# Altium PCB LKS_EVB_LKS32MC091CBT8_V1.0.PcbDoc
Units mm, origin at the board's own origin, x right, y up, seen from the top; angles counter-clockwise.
Board outline 67 x 40.5 mm, 2 copper layers (Top Layer, Bottom Layer); 59 components, 69 nets, 218 pads, 289 vias.
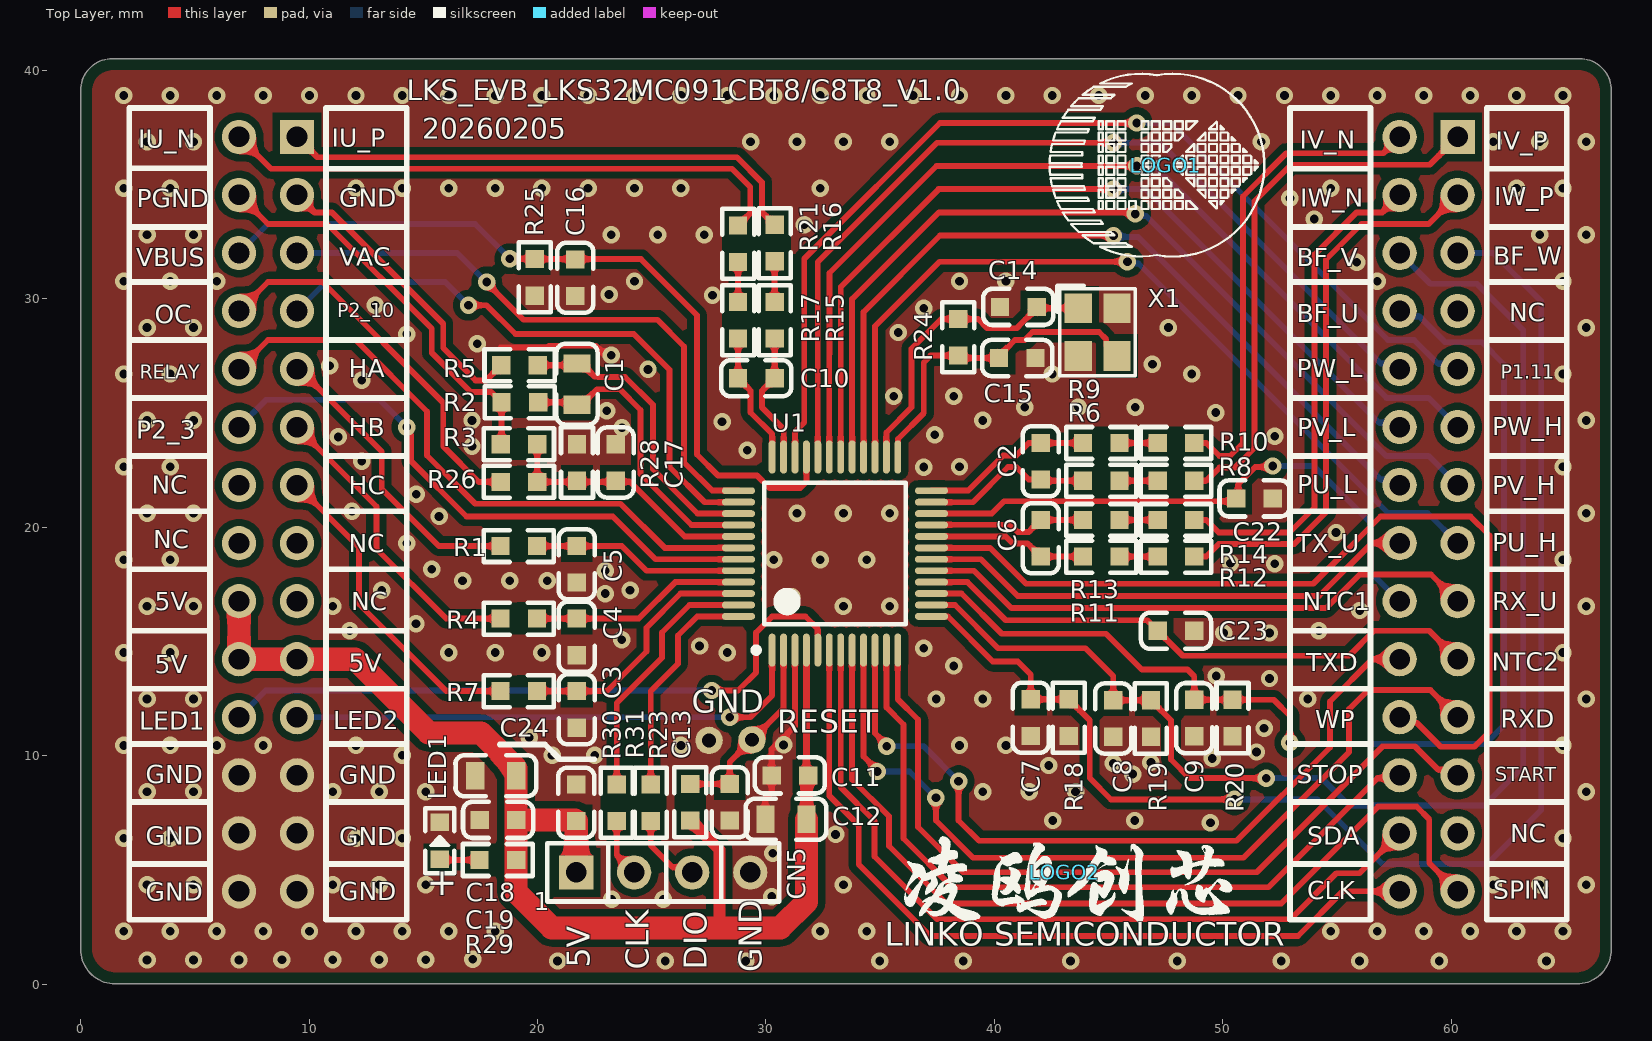
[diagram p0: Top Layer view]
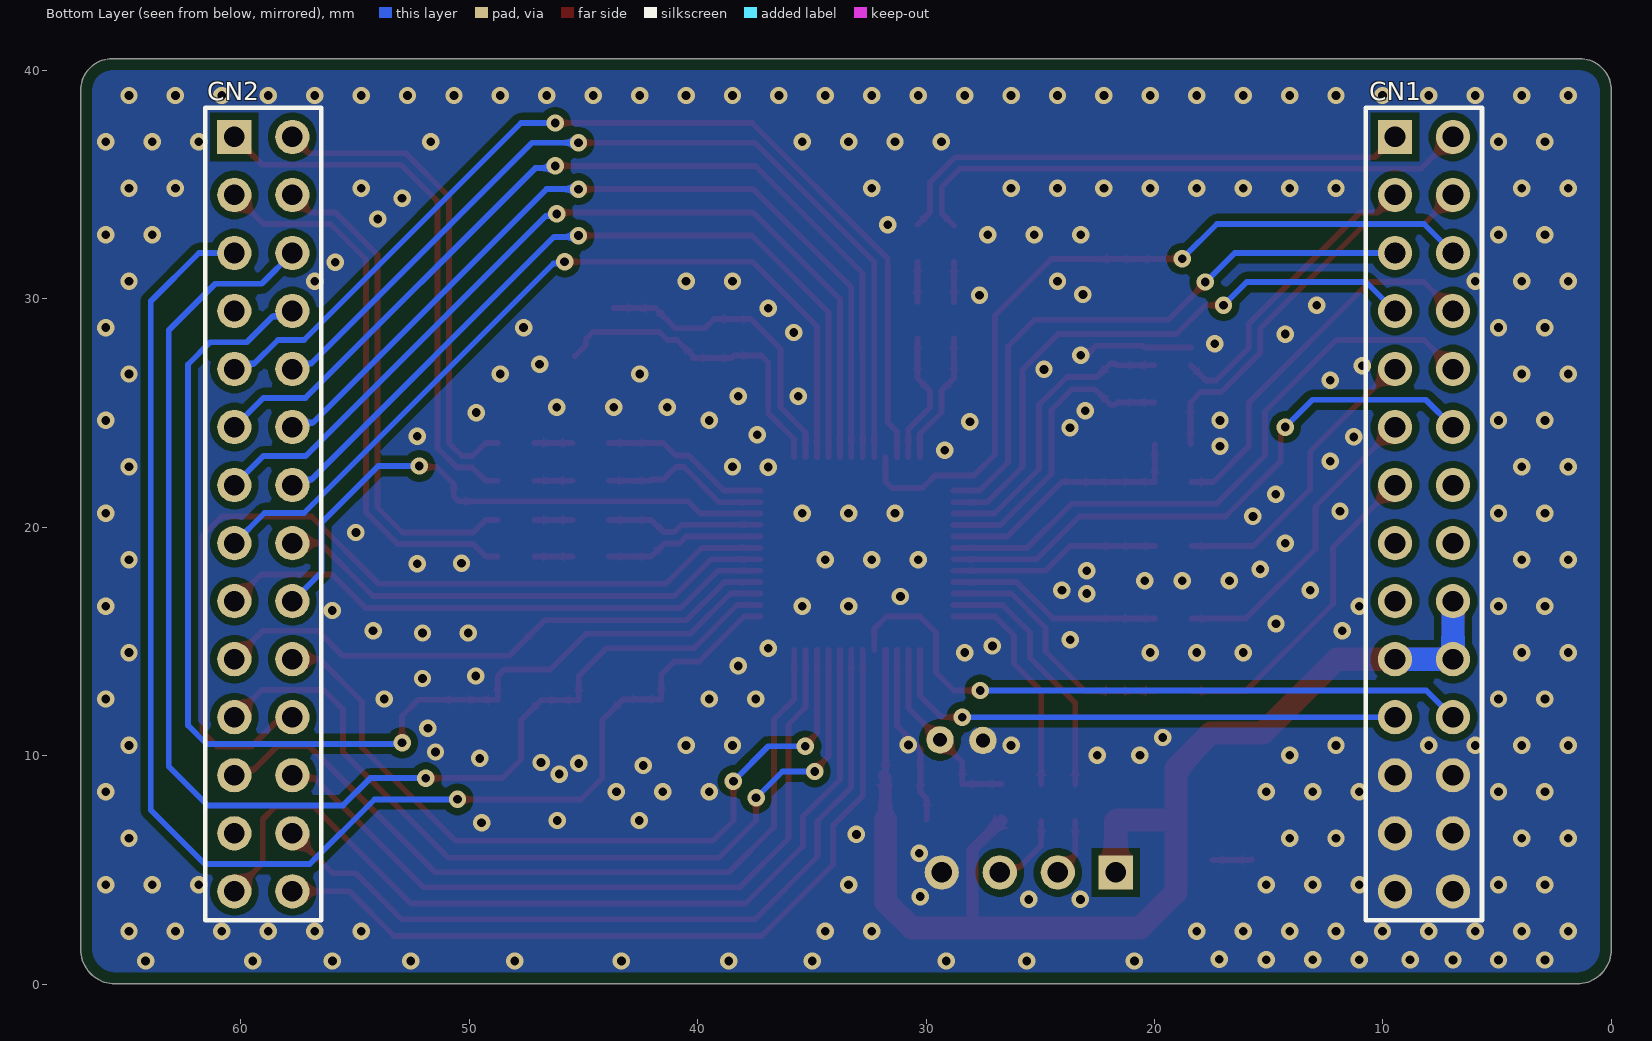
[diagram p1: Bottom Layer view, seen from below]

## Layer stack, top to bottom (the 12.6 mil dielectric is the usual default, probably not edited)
Top Solder: solder mask 0.0102, Solder Resist, Dk 3.5
Top Layer: signal copper 0.0356
Dielectric1: dielectric 0.32, FR-4, Dk 4.8
Bottom Layer: signal copper 0.0356
Bottom Solder: solder mask 0.0102, Solder Resist, Dk 3.5

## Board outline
0,1.533 0,39.116 cw(c1.397,39.116) 1.397,40.513 65.608,40.513 cw(c65.608,39.116) 67.005,39.116 67.005,1.533 cw(c65.481,1.533) 65.481,0.009 1.524,0.009 cw(c1.524,1.533)

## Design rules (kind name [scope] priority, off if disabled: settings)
BoardOutlineClearance [All] p1: gap=0.508 ignorepadtopadclearanceinfootprint=FALSE
Clearance [InPolygon] p1: gap=0.305 ignorepadtopadclearanceinfootprint=FALSE
Clearance InMCU [WithinRoom('MCU')] p2: gap=0.147 ignorepadtopadclearanceinfootprint=FALSE
Clearance Clearance_1 [All] p3: gap=0.254 ignorepadtopadclearanceinfootprint=FALSE
ComponentClearance [All] p1: gap=0 collisioncheckmode=3 verticalgap=0 showdistances=FALSE
DiffPairsRouting [All] p1: maxlimit=0.254 minlimit=0.254 mostfreqgap=0.254 toplayer_minwidth=0.254 toplayer_maxwidth=0.381 toplayer_prefwidth=0.254 bottomlayer_minwidth=0.254 bottomlayer_maxwidth=0.381 bottomlayer_prefwidth=0.254 maxuncoupledlength=12.7
FabricationTestpoint [(IsPad And (OnTopLayer Or OnBottomLayer))] p1: side=3 testpointundercomponent=TRUE minsize=1.016 maxsize=2.54 preferedsize=1.524 minholesize=0 maxholesize=1.016 preferedholesize=0.813 testpointgrid=0.025 allowsidetop=TRUE allowsidebottom=TRUE usegrid=TRUE gridtolerance=0
HoleSize [All] p1: absolutevalues=TRUE maxlimit=2.54 minlimit=0 maxpercent=80.000 minpercent=20.000
PolygonConnect [All] p1: connectstyle=Direct reliefconductorwidth=0.254 reliefentries=4 polygonreliefangle="90 Angle" airgapwidth=0.254
RoomDefinition MCU [False] p1: confinementstyle=ConfineIn formatcopy=TRUE lockcomponents=FALSE outline 19.787,37.287 41.199,37.287 41.199,1.168 19.787,1.168
RoutingVias [All] p1: holewidth=0.711 width=1.27 viastyle="Through Hole" minholewidth=0 minwidth=0.254 maxholewidth=0.711 maxwidth=1.27
SilkToSilkClearance [All] p1: silktosilkclearance=0.025
SilkToSolderMaskClearance [IsPad] p1: minsilkscreentomaskgap=0 clearancetoexposedcopper=FALSE
SilkToSolderMaskClearance SilkscreenOverComponentPads [IsPad] p2: minsilkscreentomaskgap=0.254 clearancetoexposedcopper=TRUE
SolderMaskExpansion [All] p1: expansion=0.102 istentingtop=FALSE
SupplyNets "Schematic Supply Nets_1" [InNet('GND')] p1: voltage=0.000
SupplyNets "Schematic Supply Nets" [InNet('+5V')] p2: voltage=0.000
Width [All] p1: maxlimit=2.54 minlimit=0.254 preferedwidth=0.254 minimp=50.000000 maximp=50.000000 favimp=50.000000
24 further rules are at their usual default settings.

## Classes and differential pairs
differential pair SHUNT_W: +SHUNT_W_P -SHUNT_W_N
differential pair SHUNT_V: +SHUNT_V_P -SHUNT_V_N
differential pair SHUNT_U: +SHUNT_U_P -SHUNT_U_N
differential pair OP_IW: +OP_IW_P -OP_IW_N
differential pair OP_IV: +OP_IV_P -OP_IV_N
differential pair OP_IU: +OP_IU_P -OP_IU_N
differential pair OP_IBUS: +OP_IBUS_P -OP_IBUS_N

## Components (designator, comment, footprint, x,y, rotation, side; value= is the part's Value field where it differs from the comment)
C1 "1uF/0805/50V" C0805S 21.729,26.264 r270 top
C2 "100pF/0603/50V" C0603S 42.025,22.887 r270 top
C3 "10nF/0603/50V" C0603S 21.719,12.027 r90 top
C4 "10nF/0603/50V" C0603S 21.717,15.202 r90 top
C5 "10nF/0603/50V" C0603S 21.719,18.377 r90 top
C6 "100pF/0603/50V" C0603S 42.025,19.516 r270 top
C7 "1nF/0603/50V" C0603S 41.591,11.666 r90 top
C8 "1nF/0603/50V" C0603S 45.197,11.628 r90 top
C9 "1nF/0603/50V" C0603S 48.75,11.646 r90 top
C10 "100pF/0603/50V" C0603S 29.578,26.518 r0 top
C11 "100nF/0603/50V" C0603S 31.047,9.136 r180 top
C12 "10uF/0805/25V" C0805S 30.875,7.214 r180 top
C13 "100nF/0603/50V" C0603S 28.414,7.963 r90 top
C14 "10pF/0603/50V/C0G" C0603S 41.046,29.642 r0 top
C15 "10pF/0603/50V/C0G" C0603S 40.996,27.407 r180 top
C16 "100nF/0603/50V" C0603S 21.656,30.918 r90 top
C17 "1nF/0603/50V" C0603S 23.419,22.835 r270 top
C18 "10uF/0805/25V" C0805S 18.175,9.123 r0 top
C19 "100nF/0603/50V" C0603S 18.275,7.188 r0 top
C22 "100nF/0603/50V" C0603S 51.384,21.26 r180 top
C23 "100nF/0603/50V" C0603S 47.947,15.469 r180 top
C24 "100nF/0603/50V" C0603S 21.692,7.938 r90 top
CN1 "HDR-2*14P-2.54" HDR2X14/2.54-F-B 9.474,37.084 r270 bottom
CN2 "HDR-2*14P-2.54" HDR2X14/2.54-F-B 60.274,37.084 r270 bottom
CN5 "HDR-1*4P-2.54" HDR-1*4P-2.54 26.772,4.89 r0 top
LED1 "RED" LED0603 15.723,5.461 r270 top
LOGO1 "LKS_sign" LKS_LOGO2 47.473,35.839 r0 top
LOGO2 "LKS_sign" LKS_LOGO1 43.053,4.902 r0 top
R1 "1K/0603/±5%" R0603S 19.177,19.177 r0 top
R2 "1K/0603/±1%" R0603S 19.227,25.464 r0 top
R3 "1K/0603/±1%" R0603S 19.187,23.634 r180 top
R4 "1K/0603/±5%" R0603S 19.177,16.002 r0 top
R5 "1K/0603/±1%" R0603S 19.214,27.09 r0 top
R6 "0R/0603/±5%" R0603S 44.671,22.036 r180 top
R7 "1K/0603/±5%" R0603S 19.177,12.827 r0 top
R8 "1K/0603/±1%" R0603S 47.947,22.036 r180 top
R9 "0R/0603/±5%" R0603S 44.671,23.687 r180 top
R10 "1K/0603/±1%" R0603S 47.947,23.687 r180 top
R11 "0R/0603/±5%" R0603S 44.671,18.716 r180 top
R12 "1K/0603/±1%" R0603S 47.947,18.716 r180 top
R13 "0R/0603/±5%" R0603S 44.671,20.316 r180 top
R14 "1K/0603/±1%" R0603S 47.947,20.316 r180 top
R15 "0R/0603/±5%" R0603S 30.378,29.058 r270 top
R16 "1K/0603/±1%" R0603S 30.378,32.436 r270 top
R17 "0R/0603/±5%" R0603S 28.778,29.058 r270 top
R18 "1K/0603/±1%" R0603S 43.254,11.666 r90 top
R19 "1K/0603/±1%" R0603S 46.848,11.628 r90 top
R20 "1K/0603/±1%" R0603S 50.419,11.646 r90 top
R21 "1K/0603/±1%" R0603S 28.778,32.41 r270 top
R23 "10K/0603/±5%" R0603S 26.683,7.963 r270 top
R24 "1M/0603/±5%" R0603S 38.417,28.312 r90 top
R25 "1K/0603/±1%" R0603S 19.877,30.937 r90 top
R26 "1K/0603/±1%" R0603S 19.187,21.983 r0 top
R28 "10K/0603/±1%" R0603S 21.729,22.834 r270 top
R29 "1K/0603/±5%" R0603S 18.264,5.435 r180 top
R30 "100R/0603/±5%" R0603S 23.47,7.938 r270 top
R31 "100R/0603/±5%" R0603S 24.957,7.938 r270 top
U1 "LKS32MC091CBT8/C8T8" "TQFP48 7x7" 33.02,18.847 r90 top
X1 "8MHz" XTAL-SMD3225 44.513,28.541 r270 top

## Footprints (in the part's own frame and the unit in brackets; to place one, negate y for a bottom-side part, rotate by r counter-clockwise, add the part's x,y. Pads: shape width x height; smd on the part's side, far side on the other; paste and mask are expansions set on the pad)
C0603S [mm]
  rect 0.8x0.8 smd: 1(-0.8,0) 2(0.8,0)
  silkscreen extent -1.53,-0.79 1.54,0.79, body extent -0.8,-0.4 0.8,0.4, height 0.3
C0805S [mm]
  rect 0.8x1.2 smd: 1(-0.9,0) 2(0.9,0)
  silkscreen extent -1.77,-0.9 1.77,0.9, body extent -1,-0.62 1,0.63, height 0.77
HDR2X14/2.54-F-B [mm] "Connector; Header; 14x2 Position"
  rect 1.5x1.5 hole 0.9: 1(0,0)
  round 1.5 hole 0.9: 2(0,2.54) 3(2.54,0) 4(2.54,2.54) 5(5.08,0) 6(5.08,2.54) 7(7.62,0) 8(7.62,2.54) 9(10.16,0) 10(10.16,2.54) 11(12.7,0) 12(12.7,2.54) 13(15.24,0) 14(15.24,2.54) 15(17.78,0) 16(17.78,2.54) 17(20.32,0) 18(20.32,2.54) 19(22.86,0) 20(22.86,2.54) 21(25.4,0) 22(25.4,2.54) 23(27.94,0) 24(27.94,2.54) 25(30.48,0) 26(30.48,2.54) 27(33.02,0) 28(33.02,2.54)
  silkscreen extent -1.27,-1.27 34.29,3.81, body extent -1.27,-1.27 34.29,3.81, height 8.5
HDR-1*4P-2.54 [mm]
  rect 1.5x1.5 hole 0.9: 1(-5.08,0)
  round 1.5 hole 0.9: 2(-2.54,0) 3(0,0) 4(2.54,0)
  silkscreen extent -6.35,-1.27 3.81,1.27, body extent -6.22,-1.27 3.94,1.27, height 8.54
LED0603 [mil]
  rect 30x32 smd: 1(0,0) 2(-64,0)
  silkscreen extent -88,-25 24,25, body extent -63,-16 0,16, height 24
LKS_LOGO1 [mm]
  silkscreen extent -7,-2.23 7.36,1.57
LKS_LOGO2 [mm]
  silkscreen extent -5.06,-3.99 4.34,4.01
R0603S [mm]
  rect 0.8x0.8 smd: 1(-0.8,0) 2(0.8,0)
  silkscreen extent -1.53,-0.7 1.54,0.7, body extent -0.85,-0.4 0.85,0.4, height 0.56
"TQFP48 7x7" [mm]
  oval 1.45x0.3 smd: 1(-4.225,2.75) 2(-4.225,2.25) 3(-4.225,1.75) 4(-4.225,1.25) 5(-4.225,0.75) 6(-4.225,0.25) 7(-4.225,-0.25) 8(-4.225,-0.75) 9(-4.225,-1.25) 10(-4.225,-1.75) 11(-4.225,-2.25) 12(-4.225,-2.75) 25(4.225,-2.75) 26(4.225,-2.25) 27(4.225,-1.75) 28(4.225,-1.25) 29(4.225,-0.75) 30(4.225,-0.25) 31(4.225,0.25) 32(4.225,0.75) 33(4.225,1.25) 34(4.225,1.75) 35(4.225,2.25) 36(4.225,2.75)
  oval 0.3x1.45 smd: 13(-2.75,-4.225) 14(-2.25,-4.225) 15(-1.75,-4.225) 16(-1.25,-4.225) 17(-0.75,-4.225) 18(-0.25,-4.225) 19(0.25,-4.225) 20(0.75,-4.225) 21(1.25,-4.225) 22(1.75,-4.225) 23(2.25,-4.225) 24(2.75,-4.225) 37(2.75,4.225) 38(2.25,4.225) 39(1.75,4.225) 40(1.25,4.225) 41(0.75,4.225) 42(0.25,4.225) 43(-0.25,4.225) 44(-0.75,4.225) 45(-1.25,4.225) 46(-1.75,4.225) 47(-2.25,4.225) 48(-2.75,4.225)
  silkscreen extent -4.35,-3.1 3.1,3.57, body extent -4.5,-4.51 4.5,4.5, height 1.05
XTAL-SMD3225 [mm]
  rect 1.3x1.2 smd: 1(-1.05,-0.85) 2(1.05,-0.85) 3(1.05,0.85) 4(-1.05,0.85)
  silkscreen extent -2.03,-1.75 1.91,1.65, body extent -1.47,-1.27 1.73,1.23, height 0.7

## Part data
C1: library part 贴片电容\1uF\0805\25V\K, "493950200049"
C2 C6 C10: library part 贴片电容\100pF\0603\50V\K\X7R, "493950200009"
C3 C4 C5: library part 贴片电容\10nF\0603\50V\K\X7R, "493950200014"
C7 C8 C9 C17: library part 贴片电容\1nF\0603\50V\K\X7R, "WHP"
C11 C13 C16 C19 C22 C23 C24: library part 贴片电容\100nF\0603\50V\K\X7R, "493950200070"
C12 C18: library part 贴片电容\10uF\0805\25V\K\X5R, "493950200052"
C14 C15: library part 贴片电容\10pF\0603\50V\C0G, "C1634"
CN1 CN2: library part 插座\排针\双排\2.54\180度\2*14PIN, "C2894975"
CN5: library part 插座\排针\单排\2.54\180度\4PIN, "493930100259"
LED1: library part 发光二极管\贴片\XY-DA0603HRK-620D\RED, "493920100058"
R1 R4 R7 R29: library part 贴片电阻\1K±5%\0603, "493960700021"
R2 R3 R5 R8 R10 R12 R14 R16 R18 R19 R20 R21 R25 R26: library part 贴片电阻\1K±1%\0603, "493960700020"
R6 R9 R11 R13 R15 R17: library part 贴片电阻\0R±5%\0603, "493960700009"
R23: library part 贴片电阻\10K±5%\0603, "493960700034"
R24: library part 贴片电阻\1M±5%\0603, "493960700050"
R28: library part 贴片电阻\10K±1%\0603, "493960700033"
R30 R31: library part 贴片电阻\100R±5%\0603, "493960700012"
U1: library part MCU\LKS32MC091CBT8/C8T8\TQFP48
X1: library part 晶体\SMD3225\8.0MHz\12pF\±10ppm, "C2973805"

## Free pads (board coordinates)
  round 1.2 hole 0.6: 2(29.388,10.693) 3(27.508,10.668)

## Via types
v1: diameter 0.762, hole 0.381, Top Layer to Bottom Layer, tented both sides, 289 vias

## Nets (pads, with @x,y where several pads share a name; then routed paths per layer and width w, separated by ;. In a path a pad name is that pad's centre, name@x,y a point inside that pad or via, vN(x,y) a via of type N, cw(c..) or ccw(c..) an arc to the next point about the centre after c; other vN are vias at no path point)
+5V: C11.1 C12.1 C18.2 C19.2 C24.1 CN1.18 CN1.19 CN1.20 CN5.1 R23.2 R29.1 U1.4 | length 62.1
  Top Layer w0.305: C11.1@31.77,9.213 U1.4
  Top Layer w0.508: R23.2 27.965,5.881 27.965,2.591 28.092,2.464 ; C12.1 31.775,9.065 C11.1
  Top Layer w1.016: CN1.18 CN1.20 CN1.19 12.014,14.224 15.24,10.998 17.511,10.998 19.064,9.445 19.064,7.188 R29.1 19.064,4.024 20.625,2.464 28.092,2.464 30.632,2.464 31.775,3.607 C12.1 ; C19.2 21.641,7.188 C24.1 CN5.1
  Bottom Layer w1.016: CN1.18 CN1.20 CN1.19
Amb_TEMP: C22.2 CN2.18 U1.22 | length 25.4
  Top Layer w0.254: U1.22 39.886,20.597 40.422,21.133 43.764,21.133 50.457,21.133 50.67,21.346 50.67,21.892 51.414,22.635 52.132,22.635 v1(52.176,22.679)
  Bottom Layer w0.254: v1(52.176,22.679) 53.978,22.679 56.464,20.193 56.464,18.034 CN2.18
BEMF_U: C9.2 CN2.8 R20.2 U1.15 | length 50.7
  Top Layer w0.254: U1.15 38.56,17.097 40.315,15.342 44.882,15.342 46.457,13.767 48.456,13.767 48.75,13.473 C9.2 R20.2 52.222,12.446 52.934,11.735 v1(52.934,10.566)
  Bottom Layer w0.254: v1(52.934,10.566) 52.984,10.516 61.493,10.516 62.306,11.328 62.306,27.127 61.341,28.092 59.728,28.092 58.591,29.23 57.969,29.23 CN2.8
BEMF_V: C8.2 CN2.6 R19.2 U1.14 | length 57.8
  Top Layer w0.254: U1.14 38.271,16.597 40.161,14.707 43.98,14.707 45.197,13.489 C8.2 R19.2 47.121,12.155 47.727,11.55 47.727,9.83 48.539,9.017 v1(51.892,9.017)
  Bottom Layer w0.254: v1(51.892,9.017) 54.33,9.017 55.524,7.823 61.443,7.823 63.144,9.525 63.144,28.626 61.112,30.658 59.08,30.658 CN2.6
BEMF_W: C7.2 CN2.5 R18.2 U1.13 | length 61.1
  Top Layer w0.254: U1.13 37.254,16.088 37.963,16.088 39.929,14.122 41.021,14.122 41.591,13.553 C7.2 R18.2 44.171,11.549 44.171,9.019 45.101,8.088 v1(50.507,8.088)
  Bottom Layer w0.254: v1(50.507,8.088) 54.142,8.088 56.972,5.258 61.57,5.258 63.932,7.62 63.932,29.896 61.824,32.004 CN2.5
GND: C3.1 C4.1 C5.1 C7.1 C8.1 C9.1 C11.2 C12.2 C13.1 C14.1 C15.1 C16.1 C17.1 C18.1 C19.1 C22.1 C23.1 C24.2 CN1.23 CN1.24 CN1.25 CN1.26 CN1.27 CN1.28 CN5.4 LED1.2 pad.3 R18.1 R19.1 R20.1 R25.1 R28.1 U1.3 X1.2 X1.4 | length 13
  Top Layer w0.254: 18.389,27.871 20.436,27.871 20.511,27.946 22.557,27.946 22.883,27.62 22.962,27.62 23.133,27.62 v1(23.23,27.523) ; C12.2 29.965,7.224 29.965,8.114 30.247,8.395 C11.2 30.247,10.282 31.27,11.306 U1.3
  other v1: 20.879,1.016 25.597,1.016 29.108,1.016 34.976,1.016 38.633,1.016 43.332,1.016 48.006,1.016 52.553,1.016 55.982,1.016 59.47,1.016 64.16,1.016 2.91,1.056 4.942,1.056 6.934,1.056 8.814,1.067 11.038,1.067 13.07,1.067 15.102,1.067 17.17,1.092 1.894,2.322 3.926,2.322 5.958,2.322 7.99,2.322 10.022,2.322 12.054,2.322 14.086,2.322 16.118,2.322 18.15,2.322 32.374,2.322 34.406,2.322 54.726,2.322 56.758,2.322 58.79,2.322 60.822,2.322 62.854,2.322 64.886,2.322 23.241,3.708 25.502,3.708 30.247,3.835 2.91,4.354 4.942,4.354 11.038,4.354 13.07,4.354 15.102,4.354 33.39,4.354 61.838,4.354 63.87,4.354 65.902,4.354 30.293,5.734 1.894,6.386 3.926,6.386 12.054,6.386 14.086,6.386 64.886,6.386 33.045,6.553 49.454,7.061 42.554,7.163 46.144,7.163 2.91,8.418 4.942,8.418 11.038,8.418 13.07,8.418 15.102,8.418 39.486,8.418 41.518,8.418 43.55,8.418 65.902,8.418 46.05,9.195 42.381,9.572 45.197,9.661 46.848,9.703 49.54,9.881 14.086,10.023 20.637,10.023 22.507,10.023 51.471,10.16 1.894,10.45 3.926,10.45 5.958,10.45 7.99,10.45 12.054,10.45 26.278,10.45 38.47,10.45 40.502,10.45 64.886,10.45 30.77,10.47 19.634,10.795 51.802,11.204 2.91,12.482 4.942,12.482 37.454,12.482 39.486,12.482 53.71,12.482 65.902,12.482 52.04,13.38 49.714,13.489 38.22,13.929 1.894,14.514 3.926,14.514 16.118,14.514 18.15,14.514 20.182,14.514 28.31,14.514 64.886,14.514 36.903,14.707 27.094,14.802 23.69,15.077 50.04,15.371 52.04,15.371 11.785,15.469 54.204,15.469 14.681,15.773 55.987,16.357 2.91,16.546 4.942,16.546 11.038,16.546 33.39,16.546 35.422,16.546 65.902,16.546 31.121,16.97 22.962,17.097 24.051,17.242 13.183,17.247 16.721,17.657 18.787,17.657 20.428,17.657 22.962,18.097 15.372,18.161 52.266,18.405 50.331,18.426 1.894,18.578 3.926,18.578 30.342,18.578 32.374,18.578 34.406,18.578 64.886,18.578 14.275,19.304 54.952,19.77 15.691,20.472 2.91,20.61 4.942,20.61 31.358,20.61 33.39,20.61 35.422,20.61 65.902,20.61 11.881,20.701 14.696,21.438 1.894,22.642 3.926,22.642 36.906,22.633 38.47,22.642 64.886,22.642 12.311,22.884 29.178,23.365 17.134,23.542 11.278,23.952 52.266,23.977 37.389,24.047 23.698,24.359 28.078,24.613 2.91,24.674 4.942,24.674 17.134,24.674 39.486,24.674 65.902,24.674 49.682,25.019 23.029,25.098 41.32,25.248 43.663,25.248 46.164,25.248 35.593,25.728 38.22,25.728 12.311,26.428 1.894,26.706 3.926,26.706 42.534,26.706 48.63,26.706 64.886,26.706 24.835,26.908 10.905,27.063 46.914,27.127 17.359,28.035 14.275,28.454 35.789,28.524 2.91,28.738 4.942,28.738 47.614,28.738 65.902,28.738 36.906,29.582 12.899,29.718 27.661,30.15 23.133,30.185 1.894,30.77 3.926,30.77 5.958,30.77 24.246,30.77 38.47,30.77 40.502,30.77 56.758,30.77 64.886,30.77 55.855,31.597 2.91,32.802 4.942,32.802 23.23,32.802 25.262,32.802 27.294,32.802 63.87,32.802 65.902,32.802 31.674,33.236 54.004,33.489 52.934,34.405 1.894,34.834 3.926,34.834 12.054,34.834 14.086,34.834 16.118,34.834 18.15,34.834 20.182,34.834 22.214,34.834 24.246,34.834 26.278,34.834 32.374,34.834 54.726,34.834 62.854,34.834 64.886,34.834 2.91,36.866 4.942,36.866 29.326,36.866 31.358,36.866 33.39,36.866 35.422,36.866 51.678,36.866 61.838,36.866 63.87,36.866 65.902,36.866 1.894,38.898 3.926,38.898 5.958,38.898 7.99,38.898 10.022,38.898 12.054,38.898 14.086,38.898 16.118,38.898 18.15,38.898 20.182,38.898 22.214,38.898 24.246,38.898 26.278,38.898 28.31,38.898 30.342,38.898 32.374,38.898 34.406,38.898 36.438,38.898 38.47,38.898 40.502,38.898 42.534,38.898 44.566,38.898 46.598,38.898 48.63,38.898 50.662,38.898 52.694,38.898 54.726,38.898 56.758,38.898 58.79,38.898 60.822,38.898 62.854,38.898 64.886,38.898
GND1: CN1.3 R5.1 | length 13.2
  Top Layer w0.254: CN1.3 10.236,33.782 10.998,33.782 15.875,28.905 15.875,27.843 17.289,26.428 17.753,26.428 R5.1
HALL_A: CN1.9 R1.1 | length 13.1
  Top Layer w0.254: CN1.9 9.569,26.924 13.183,23.311 13.183,21.677 15.683,19.177 R1.1
HALL_B: CN1.11 R4.1 | length 13.5
  Top Layer w0.254: CN1.11 12.954,20.904 12.954,19.05 16.002,16.002 R4.1
HALL_C: CN1.13 R7.1 | length 14.1
  Top Layer w0.254: CN1.13 12.192,19.126 12.192,16.637 16.002,12.827 R7.1
HALL_MA: C5.2 R1.2 U1.44 | length 9.3
  Top Layer w0.254: R1.2 C5.2 22.962,19.177 23.69,19.177 24.77,18.097 U1.44
HALL_MB: C4.2 R4.2 U1.45 | length 9.5
  Top Layer w0.254: R4.2 C4.2 22.962,16.002 24.435,16.002 26.03,17.597 U1.45
HALL_MC: C3.2 R7.2 U1.46 | length 11.2
  Top Layer w0.254: R7.2 C3.2 23.038,12.827 24.77,14.559 24.77,15.604 26.262,17.097 U1.46
IGBT_TEMP: C23.2 CN2.19 U1.16 | length 25.3
  Top Layer w0.254: U1.16 38.822,17.597 40.493,15.926 43.764,15.926 46.69,15.926 C23.2 48.239,14.376 55.524,14.376 56.617,15.469 59.03,15.469 CN2.19
IIC_CLK: CN2.28 U1.6 | length 35.7
  Top Layer w0.254: U1.6 32.77,8.251 34.061,6.96 34.061,5.232 37.186,2.108 53.289,2.108 55.245,4.064 CN2.28
IIC_SDA: CN2.26 U1.7 | length 35.3
  Top Layer w0.254: U1.7 33.27,8.615 34.747,7.137 34.747,5.588 37.49,2.845 52.959,2.845 54.966,4.851 55.982,4.851 CN2.26
IIC_WP: CN2.22 U1.19 | length 40
  Top Layer w0.254: U1.19 39.807,19.097 41.378,17.526 43.764,17.526 53.951,17.526 56.9,20.475 60.83,20.475 61.671,19.634 61.671,11.049 61.011,10.389 59.538,10.389 58.481,11.446 57.973,11.446 CN2.22
ITRIP: C17.2 R3.1 R26.2 R28.2 U1.41 | length 11.5
  Top Layer w0.254: R3.1 R26.2 21.729,21.983 23.454,21.983 23.462,21.991 24.051,21.991 26.445,19.597 U1.41
LED1: CN1.22 U1.5 | length 29.3
  Top Layer w0.254: v1(27.624,12.852) 28.776,12.852 29.57,13.647 29.57,15.397 30.27,16.097 31.73,16.097 32.27,15.557 U1.5
  Bottom Layer w0.254: CN1.22 8.103,12.852 22.962,12.852 v1(27.624,12.852)
LED2: CN1.21 U1.1 | length 23.2
  Top Layer w0.254: v1(28.414,11.684) 29.317,11.684 30.27,12.637 U1.1
  Bottom Layer w0.254: CN1.21 22.962,11.684 v1(28.414,11.684)
NetC14_2: C14.2 R24.2 U1.26 X1.1 | length 13.6
  Top Layer w0.254: U1.26 35.27,24.145 36.373,25.248 36.373,27.813 37.672,29.112 39.284,29.112 39.684,28.712 40.976,28.712 41.199,28.936 41.846,29.582 41.854,29.591 X1.1
NetC15_2: C15.2 R24.1 U1.25 X1.3 | length 14.3
  Top Layer w0.254: U1.25 35.779,23.081 35.779,23.866 36.906,24.994 36.906,27.212 37.207,27.512 R24.1 38.522,27.407 C15.2 ; C15.2@40.193,27.491 40.898,28.197 41.323,28.197 41.668,28.541 44.572,28.541 44.89,28.223 44.89,27.964 X1.3
NetCN5_2: CN5.2 R30.2 | length 2.6
  Top Layer w0.254: R30.2 23.47,5.652 CN5.2
NetCN5_3: CN5.3 R31.2 | length 3.4
  Top Layer w0.254: R31.2 24.957,6.07 25.908,5.118 26.543,5.118 CN5.3
NetLED1_1: LED1.1 R29.2 | length 1.8
  Top Layer w0.254: LED1.1 15.748,5.435 R29.2
NetR6_1: R6.1 R8.2 | length 1.7
  Top Layer w0.254: R6.1 R8.2
NetR9_1: R9.1 R10.2 | length 1.7
  Top Layer w0.254: R9.1 R10.2
NetR11_1: R11.1 R12.2 | length 1.7
  Top Layer w0.254: R11.1 R12.2
NetR13_1: R13.1 R14.2 | length 1.7
  Top Layer w0.254: R13.1 R14.2
NetR15_1: R15.1 R16.2 | length 1.8
  Top Layer w0.254: R15.1 R16.2
NetR17_1: R17.1 R21.2 | length 1.8
  Top Layer w0.254: R17.1 R21.2
NRST: C13.2 pad.2 R23.1 U1.2 | length 8.6
  Top Layer w0.254: R23.1 C13.2 28.414,9.719 30.77,12.076 U1.2
OC: CN1.8 R26.1 | length 16.7
  Top Layer w0.254: CN1.8 8.204,30.734 10.594,30.734 15.875,25.453 15.875,23.542 17.434,21.983 R26.1
OP_IBUS_N: C1.1 R5.2 U1.39 | length 13.2
  Top Layer w0.254: R5.2 21.654,27.09 C1.1 21.929,27.164 22.51,26.584 22.64,26.584 22.644,26.58 23.83,26.58 25.052,25.358 25.052,22.552 27.008,20.597 U1.39
OP_IBUS_P: C1.2 R2.2 U1.40 | length 13.2
  Top Layer w0.254: R2.2 21.629,25.464 C1.2 21.929,25.364 22.606,26.041 23.607,26.041 24.513,25.135 24.513,22.329 26.746,20.097 U1.40
OP_IU_N: C10.1 R17.2 U1.36 | length 5.8
  Top Layer w0.254: R17.2 C10.1 29.324,25.972 29.324,25.024 30.27,24.079 U1.36
OP_IU_P: C10.2 R15.2 U1.35 | length 5.8
  Top Layer w0.254: R15.2 C10.2 29.832,25.972 29.832,25.235 30.778,24.289 U1.35@30.778,23.072
OP_IV_N: C2.1 R9.2 U1.24 | length 7.5
  Top Layer w0.254: U1.24@37.245,21.605 38.849,21.605 40.386,23.141 40.952,23.141 41.498,23.687 C2.1 R9.2
OP_IV_P: C2.2 R6.2 U1.23 | length 7.5
  Top Layer w0.254: U1.23 39.06,21.097 40.596,22.633 40.952,22.633 41.498,22.087 C2.2 42.076,22.036 R6.2
OP_IW_N: C6.1 R13.2 U1.21 | length 7
  Top Layer w0.254: U1.21@37.245,20.105 40.708,20.105 41.017,19.796 41.505,19.796 C6.1 R13.2
OP_IW_P: C6.2 R11.2 U1.20 | length 7
  Top Layer w0.254: U1.20 40.498,19.597 40.807,19.288 41.453,19.288 C6.2 R11.2
P1.11: CN2.9 U1.34 | length 44.4
  Top Layer w0.254: U1.34 31.27,24.183 31.674,24.587 31.674,31.75 32.112,32.188 37.617,37.694 v1(46.228,37.694)
  Bottom Layer w0.254: v1(46.228,37.694) 47.727,37.694 57.226,28.194 58.369,28.194 59.411,27.152 60.046,27.152 CN2.9
P2.3: CN1.12 U1.43 | length 26
  Top Layer w0.254: v1(14.275,24.384) 14.275,24.247 14.478,24.043 14.478,22.884 16.889,20.472 23.292,20.472 25.167,18.597 U1.43
  Bottom Layer w0.254: CN1.12 8.128,25.578 13.081,25.578 v1(14.275,24.384)
P2.10: CN1.7 U1.38 | length 26.3
  Top Layer w0.254: v1(16.978,29.718) 17.769,29.718 19.033,28.454 24.216,28.454 25.781,26.888 25.781,22.631 27.316,21.097 U1.38
  Bottom Layer w0.254: CN1.7 10.744,30.734 15.962,30.734 v1(16.978,29.718)
PGND: CN1.4 R2.1 R3.2 | length 17.7
  Top Layer w0.254: CN1.4 8.204,33.274 10.788,33.274 15.367,28.695 15.367,27.632 17.079,25.92 17.971,25.92 R2.1 18.427,23.674 R3.2
PWMU_H: CN2.15 U1.27 | length 37.5
  Top Layer w0.254: U1.27 34.77,28.801 37.592,31.623 v1(45.822,31.623)
  Bottom Layer w0.254: v1(45.822,31.623) 45.903,31.541 46.31,31.541 57.226,20.625 58.953,20.625 CN2.15
PWMU_L: CN2.14 U1.28 | length 35.7
  Top Layer w0.254: U1.28 34.27,29.415 37.621,32.766 v1(45.212,32.766)
  Bottom Layer w0.254: v1(45.212,32.766) 45.274,32.704 46.29,32.704 56.912,22.082 57.496,22.082 CN2.14
PWMV_H: CN2.13 U1.29 | length 39.9
  Top Layer w0.254: U1.29 33.77,29.984 37.568,33.782 46.09,33.782 v1(46.159,33.713)
  Bottom Layer w0.254: v1(46.159,33.713) 46.246,33.626 46.642,33.626 57.155,23.114 59.004,23.114 CN2.13
PWMV_L: CN2.12 U1.30 | length 38
  Top Layer w0.254: U1.30 33.27,30.527 ; 33.286,30.527 37.557,34.798 v1(45.212,34.798)
  Bottom Layer w0.254: v1(45.212,34.798) 46.609,34.798 56.833,24.574 57.544,24.574 CN2.12
PWMW_H: CN2.11 U1.31 | length 42.2
  Top Layer w0.254: U1.31 32.77,27.584 32.778,27.592 32.778,31.127 37.465,35.814 v1(46.228,35.814)
  Bottom Layer w0.254: v1(46.228,35.814) 46.325,35.717 47.103,35.717 57.166,25.654 59.004,25.654 CN2.11
PWMW_L: CN2.10 U1.32 | length 40.3
  Top Layer w0.254: U1.32 32.27,31.61 37.49,36.83 v1(45.212,36.83)
  Bottom Layer w0.254: v1(45.212,36.83) 47.244,36.83 56.912,27.162 57.496,27.162 CN2.10
RELAY_C: CN1.10 U1.42 | length 27.3
  Top Layer w0.254: CN1.10 8.204,28.194 12.04,28.194 15.164,25.07 15.164,23.139 17.272,21.031 22.962,21.031 23.635,21.031 25.57,19.097 U1.42
RXD0: CN2.21 U1.9 | length 37.7
  Top Layer w0.254: U1.9 34.27,9.97 34.867,9.373 v1(34.867,9.31) ; v1(37.44,8.153) 37.44,7.163 39.065,5.537 43.764,5.537 50.902,5.537 55.524,10.16 55.524,12.04 56.363,12.878 59.08,12.878 CN2.21
  Bottom Layer w0.254: v1(34.867,9.31) 36.283,9.31 v1(37.44,8.153)
RXD_U: CN2.17 U1.17 | length 24.8
  Top Layer w0.254: U1.17 39.104,18.097 40.742,16.459 43.764,16.459 54.512,16.459 55.987,17.935 59.103,17.935 CN2.17
SHUNT_U_N: CN1.2 R21.1 | length 25.2
  Top Layer w0.254: CN1.2 8.331,35.687 28.517,35.687 29.312,34.892 29.312,33.743 R21.1
SHUNT_U_P: CN1.1 R16.1 | length 23.3
  Top Layer w0.254: CN1.1 10.363,36.195 28.727,36.195 29.82,35.103 29.82,33.795 R16.1
SHUNT_V_N: CN2.2 R10.1 | length 21.3
  Top Layer w0.254: R10.1 49.274,23.687 49.845,23.116 50.311,23.116 50.876,23.681 50.876,34.475 52.774,36.373 57.023,36.373 CN2.2
SHUNT_V_P: CN2.1 R8.1 | length 24.1
  Top Layer w0.254: R8.1 49.274,22.036 49.845,22.608 50.522,22.608 51.384,23.47 51.384,34.265 52.984,35.865 59.055,35.865 CN2.1
SHUNT_W_N: CN2.4 R14.1 | length 21.8
  Top Layer w0.254: R14.1 49.274,20.316 49.82,19.77 52.911,19.77 54.004,20.863 54.004,31.931 55.855,33.782 56.972,33.782 CN2.4
SHUNT_W_P: CN2.3 R12.1 | length 24.6
  Top Layer w0.254: R12.1 49.274,18.716 49.82,19.262 53.122,19.262 54.512,20.652 54.512,31.721 56.065,33.274 59.004,33.274 CN2.3
SPIN: CN2.27 U1.8 | length 39.6
  Top Layer w0.254: U1.8 33.77,8.962 35.382,7.35 35.382,6.045 37.897,3.531 43.764,3.531 52.553,3.531 56.794,7.772 58.471,7.772 59.03,7.214 59.03,5.309 CN2.27
START1: CN2.23 U1.12 | length 35.4
  Top Layer w0.254: U1.12 35.77,12.466 36.652,11.584 36.652,6.883 38.633,4.902 43.764,4.902 51.486,4.902 56.998,10.414 58.395,10.414 59.426,9.382 60.036,9.382 CN2.23
STOP1: CN2.24 U1.11 | length 33.2
  Top Layer w0.254: U1.11 35.27,12.116 36.017,11.369 36.017,6.375 38.151,4.242 43.764,4.242 51.994,4.242 56.769,9.017 57.608,9.017 CN2.24
SWD_CLK: R30.1 U1.47 | length 11.3
  Top Layer w0.254: R30.1 23.47,12.305 25.451,14.286 25.451,15.397 26.651,16.597 U1.47
SWD_DIO: R31.1 U1.48 | length 10
  Top Layer w0.254: R31.1 24.957,12.827 26.151,14.021 26.151,15.26 26.988,16.097 U1.48
TXD0: CN2.20 U1.10 | length 34.1
  Top Layer w0.254: U1.10 34.77,10.981 35.281,10.47 v1(35.281,10.414) ; v1(38.43,8.887) 38.43,7.163 39.319,6.274 43.764,6.274 50.597,6.274 54.686,10.363 54.686,12.37 56.54,14.224 CN2.20
  Bottom Layer w0.254: v1(35.281,10.414) 36.903,10.414 v1(38.43,8.887)
TXD_U: CN2.16 U1.18 | length 22.1
  Top Layer w0.254: U1.18 39.417,18.597 41.021,16.993 43.764,16.993 54.204,16.993 56.515,19.304 CN2.16
VAC_ADC: CN1.5 U1.37 | length 26.6
  Top Layer w0.254: v1(17.78,30.734) 17.78,30.694 19.391,29.083 22.962,29.083 25.248,29.083 26.416,27.915 26.416,22.835 27.645,21.606 28.786,21.606 U1.37
  Bottom Layer w0.254: CN1.5 16.49,32.004 17.76,30.734 v1(17.78,30.734)
VBUS_ADC: C16.2 CN1.6 R25.2 U1.33 | length 34.9
  Top Layer w0.254: v1(18.791,31.75) 19.799,31.75 19.812,31.737 21.592,31.737 24.524,31.737 26.982,29.279 26.982,23.183 27.895,22.27 29.596,22.27 30.15,21.717 31.496,21.717 31.77,21.991 U1.33
  Bottom Layer w0.254: CN1.6 8.204,33.274 17.267,33.274 v1(18.791,31.75)
pads on no net: CN1.14 CN1.15 CN1.16 CN1.17 CN2.7 CN2.25

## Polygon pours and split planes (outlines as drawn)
GND on Bottom Layer "GND_L02_P001" (solid, remove dead copper, pour order 1): 0,1.533 0,39.116 cw(c1.397,39.116) 1.397,40.513 65.608,40.513 cw(c65.608,39.116) 67.005,39.116 67.005,1.533 cw(c65.481,1.533) 65.481,0.009 1.524,0.009 cw(c1.524,1.533)
GND on Top Layer "GND_L01_P000" (solid, remove dead copper, pour order 0): 0.141,1.149 0.141,38.732 cw(c1.538,38.732) 1.538,40.129 65.749,40.129 cw(c65.749,38.732) 67.146,38.732 67.146,1.149 cw(c65.622,1.149) 65.622,-0.375 1.665,-0.375 cw(c1.665,1.149)

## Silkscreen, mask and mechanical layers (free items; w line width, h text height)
Top Overlay:
  lines w0.254: 2.215,5.258 5.588,5.258 ; 2.215,7.976 5.588,7.976 ; 2.215,10.516 5.588,10.516 ; 2.215,12.929 5.588,12.929 ; 2.215,15.469 5.588,15.469 ; 2.215,18.161 5.588,18.161 ; 2.215,20.701 5.588,20.701 ; 2.215,23.114 5.588,23.114 ; 2.215,25.654 5.588,25.654 ; 2.215,28.194 5.588,28.194 ; 2.215,30.734 5.588,30.734 ; 2.215,33.147 5.588,33.147 ; 2.215,35.712 5.664,35.712 ; 10.744,5.258 14.118,5.258 ; 10.744,7.976 14.118,7.976 ; 10.744,10.516 14.118,10.516 ; 10.744,12.929 14.118,12.929 ; 10.744,15.469 14.118,15.469 ; 10.744,18.161 14.118,18.161 ; 10.744,20.701 14.118,20.701 ; 10.744,23.114 14.118,23.114 ; 10.744,25.654 14.118,25.654 ; 10.744,30.734 14.118,30.734 ; 10.82,33.147 14.194,33.147 ; 10.846,28.194 14.219,28.194 ; 14.118,35.687 10.744,35.687 ; 18.344,10.492 20.323,10.492 20.974,9.841 22.482,9.841 ; 52.989,5.258 56.363,5.258 ; 52.989,7.976 56.363,7.976 ; 52.989,10.516 56.363,10.516 ; 52.989,12.929 56.363,12.929 ; 52.989,15.469 56.236,15.469 ; 52.989,18.161 56.337,18.161 ; 52.989,20.701 56.363,20.701 ; 52.989,23.114 56.363,23.114 ; 52.989,25.654 56.363,25.654 ; 52.989,28.194 56.363,28.194 ; 52.989,30.734 56.363,30.734 ; 52.989,33.147 56.363,33.147 ; 52.989,35.687 56.363,35.687 ; 56.464,38.354 52.934,38.354 52.934,35.53 52.934,2.819 56.464,2.819 56.464,35.687 56.464,38.354 ; 61.544,5.258 64.918,5.258 ; 61.544,7.976 64.918,7.976 ; 61.544,10.516 64.918,10.516 ; 61.544,12.929 64.918,12.929 ; 61.544,15.469 64.918,15.469 ; 61.544,18.161 64.918,18.161 ; 61.544,20.701 64.918,20.701 ; 61.544,23.114 64.918,23.114 ; 61.544,25.654 64.918,25.654 ; 61.544,28.194 64.918,28.194 ; 61.544,30.734 64.918,30.734 ; 61.544,33.147 64.918,33.147 ; 5.664,35.712 5.664,38.354 2.134,38.354 2.134,35.53 2.134,2.819 5.664,2.819 5.664,35.712 ; 10.744,35.687 10.744,2.819 14.275,2.819 14.275,35.53 14.275,38.354 10.744,38.354 10.744,35.687 ; 61.544,35.687 65.049,35.687 ; 61.544,35.687 61.544,38.354 65.049,38.354 65.049,35.687 ; 61.544,35.687 61.544,2.819 65.049,2.819 65.049,35.687
  text "LKS_EVB_LKS32MC091CBT8/C8T8_V1.0" at 14.275,38.684 h0.89
  text "20260205" at 14.961,37.008 h0.89
  text "IU_P" at 10.995,36.652 h0.8
  text "IU_N" at 2.515,36.601 h0.8
  text "IV_N" at 53.36,36.576 h0.8
  text "IV_P" at 61.951,36.525 h0.8
  text "IW_P" at 61.874,34.087 h0.8
  text "GND" at 11.328,34.036 h0.8
  text "IW_N" at 53.377,34.036 h0.8
  text "PGND" at 2.464,34.011 h0.8
  text "BF_W" at 61.824,31.496 h0.8
  text "VAC" at 11.328,31.445 h0.8
  text "VBUS" at 2.438,31.42 h0.8
  text "BF_V" at 53.238,31.42 h0.8
  text "P2_10" at 11.227,29.185 h0.6
  text "NC" at 62.535,29.007 h0.8
  text "BF_U" at 53.238,28.981 h0.8
  text "OC" at 3.245,28.931 h0.8
  text "HA" at 11.728,26.568 h0.8
  text "PW_L" at 53.238,26.568 h0.8
  text "RELAY" at 2.591,26.492 h0.6
  text "P1.11" at 62.154,26.492 h0.6
  text "PW_H" at 61.784,24.028 h0.8
  text "HB" at 11.728,23.978 h0.8
  text "PV_L" at 53.264,23.978 h0.8
  text "P2_3" at 2.438,23.876 h0.8
  text "PU_L" at 53.264,21.488 h0.8
  text "NC" at 3.113,21.454 h0.8
  text "HC" at 11.728,21.438 h0.8
  text "PV_H" at 61.784,21.438 h0.8
  text "NC" at 3.191,19.074 h0.8
  text "PU_H" at 61.784,18.948 h0.8
  text "NC" at 11.741,18.914 h0.8
  text "TX_U" at 53.213,18.898 h0.8
  text "5V" at 3.245,16.358 h0.8
  text "NC" at 11.851,16.374 h0.8
  text "NTC1" at 53.496,16.358 h0.8
  text "RX_U" at 61.784,16.358 h0.8
  text "NTC2" at 61.773,13.716 h0.8
  text "TXD" at 53.656,13.691 h0.8
  text "5V" at 11.728,13.665 h0.8
  text "5V" at 3.245,13.614 h0.8
  text "GND" at 26.758,11.884 h1
  text "RXD" at 62.151,11.227 h0.8
  text "WP" at 54.052,11.204 h0.8
  text "LED2" at 11.049,11.151 h0.8
  text "LED1" at 2.578,11.125 h0.8
  text "RESET" at 30.493,11.013 h1
  text "START" at 61.911,8.89 h0.6
  text "GND" at 2.845,8.788 h0.8
  text "STOP" at 53.238,8.788 h0.8
  text "GND" at 11.328,8.763 h0.8
  text "NC" at 62.575,6.214 h0.8
  text "GND" at 2.845,6.096 h0.8
  text "SDA" at 53.692,6.096 h0.8
  text "GND" at 11.328,6.071 h0.8
  text "SPIN" at 61.824,3.734 h0.8
  text "CLK" at 53.692,3.708 h0.8
  text "GND" at 11.328,3.683 h0.8
  text "GND" at 2.845,3.658 h0.8
  text "5V" at 22.279,0.708 h1 r90
  text "CLK" at 24.87,0.632 h1 r90
  text "DIO" at 27.41,0.632 h1 r90
  text "GND" at 29.823,0.53 h1 r90
Mechanical 1:
  the board outline again, w0.254

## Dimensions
65.608,40.513 to 65.481,0.009 on Mechanical 15
0,39.116 to 67.005,39.116 on Mechanical 15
